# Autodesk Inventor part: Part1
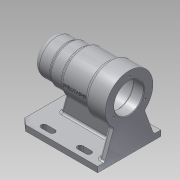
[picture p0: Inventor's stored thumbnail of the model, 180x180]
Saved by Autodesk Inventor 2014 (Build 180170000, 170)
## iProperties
Created: 2017-09
Part Number: Part1
Material: Aluminum 6061
Document SubType Name: Modeling
Designer: user
Density: 2.71 g/cm^3
Appearance: Aluminum - Flat
Author: user
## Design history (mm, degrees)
sketch "Sketch3"
  geometry: L1 (0, 0)-(0, 90); L2 (0, 90)-(112, 90); L3 (112, 90)-(112, 0); L4 (112, 0)-(0, 0)
  constraints: 8 end point
extrude "Extrusion1" new body sketch "Sketch3" distance "d0" = 8; taper "d1" = 0 deg
sketch "Sketch4"
  geometry: L1 (0, 90)-(0, 0) reference; L2 (0, 0)-(112, 0) reference; L3 (112, 90)-(0, 90) reference; L4 (56, 45)-(0, 45); L5 (0, 45)-(0, 81.946); L6 (0, 81.946)-(8.896, 90); L7 (8.896, 90)-(56, 90); L8 (56, 90)-(56, 45); L9 (0, 90)-(8.896, 90); L10 (0, 81.946)-(0, 90); L11 (56, 90)-(112, 90); L12 (0, 45)-(0, 8.054); L13 (0, 8.054)-(8.896, 0); L14 (0, 8.054)-(0, 0); L15 (0, 0)-(8.896, 0); L16 (0, 45)-(0, 81.946); L17 (0, 45)-(0, 8.054)
  constraints: 28 end point, 4 point on line, 2 midpoint
  dimensions: "d3" = 12 distance of L5.end L6.end; "d4" = 12 distance of L12.end L13.end
extrude "Extrusion2" cut sketch "Sketch4" distance "d5" = 8; taper "d6" = 0 deg
workplane "Work Plane1"
sketch "Sketch5"
  geometry: L1 (8.896, 90)-(0, 81.946) reference; L2 (0, 81.946)-(0, 8.054) reference; L3 (0, 8.054)-(8.896, 0) reference; L4 (8.896, 0)-(112, 0) reference; L5 (112, 0)-(112, 90) reference; L6 (112, 90)-(8.896, 90) reference; L7 (112, 90)-(112, 45); L8 (112, 45)-(112, 75); L9 (112, 45)-(0, 45); L10 (0, 45)-(0, 70); L11 (0, 70)-(25, 70); L12 (25, 70)-(25, 72); L13 (25, 72)-(45, 72); L14 (45, 72)-(45, 75); L15 (45, 75)-(84, 75); L16 (84, 75)-(84, 79); L17 (84, 79)-(112, 79); L18 (112, 79)-(112, 45); L19 (112, 45)-(112, 79); 1 further point
  constraints: 26 end point, 3 point on line, 2 midpoint
revolve "Revolution1" sketch "Sketch5" stored, may be unused: angle "d8" = 90 deg
sketch "Sketch6"
  geometry: C1 r 34 at (0, 0) reference; C2 r 21 at (0, 0); 1 further point
  constraints: 1 centre point, 1 coincident
extrude "Extrusion3" cut sketch "Sketch6" distance "d9" = 15; taper "d10" = 0 deg
sketch "Sketch7"
  geometry: C1 r 21 at (0, 0) reference; C2 r 24 at (0, 0); 1 further point
  constraints: 1 centre point, 1 coincident
extrude "Extrusion4" cut sketch "Sketch7" distance "d11" = 54; taper "d12" = 0 deg
sketch "Sketch8"
  geometry: C1 r 24 at (0, 0) reference; C2 r 21 at (0, 0); 1 further point
  constraints: 1 centre point, 1 coincident
extrude "Extrusion5" cut sketch "Sketch8" distance "d13" = 12; taper "d14" = 0 deg
sketch "Sketch9"
  geometry: C1 r 21 at (0, 0) reference; C2 r 17.5 at (0, 0); 1 further point
  constraints: 1 centre point, 1 coincident
extrude "Extrusion6" cut sketch "Sketch9" distance "d15" = 18; taper "d16" = 0 deg
sketch "Sketch10"
  geometry: C1 r 17.5 at (0, 0) reference; C2 r 16 at (0, 0); 1 further point
  constraints: 1 centre point, 1 coincident
extrude "Extrusion7" cut sketch "Sketch10" distance "d17" = 4; taper "d18" = 0 deg
sketch "Sketch11"
  geometry: C1 r 16 at (0, 0) reference; C2 r 10.5 at (0, 0); 1 further point
  constraints: 1 centre point, 1 coincident
extrude "Extrusion8" cut sketch "Sketch11" distance "d19" = 4; taper "d20" = 0 deg
sketch "Sketch12"
  geometry: L1 (0, 81.946)-(0, 8.054) reference; L2 (0, 45)-(0, 11); L3 (0, 11)-(24, 11); L4 (24, 11)-(36, 11); L5 (24, 15)-(36, 15); L6 (24, 7)-(36, 7); A1 r 4 centre (24, 11) between (24, 15) and (24, 7); A2 r 4 centre (36, 11) between (36, 15) and (36, 7); 1 further point
  constraints: 10 end point, 4 point on circle, 2 centre point, 2 coincident, 1 midpoint, 1 point on line
extrude "Extrusion9" cut sketch "Sketch12" distance "d21" = 8; taper "d22" = 0 deg
pattern_linear "Rectangular Pattern1" dims "d25" = -68, "d28" = 52
sketch "Sketch13"
  geometry: C1 r 34 at (0, 0) reference; 3 further points
  constraints: 1 coincident, 1 horizontal alignment, 2 other
hole "Hole1" sketch "Sketch13" at (-26, 0) diameter "d29" = 3.242; stored, may be unused: countersink angle "d33" = 90 deg, drill point angle "d35" = 118 deg; dims "d30" = 8, "d31" = 11, "d32" = 2, "d34" = 11
pattern_circular "Circular Pattern1" dims angle "d37" = 360 deg
workplane "Work Plane2"
sketch "Sketch15"
  geometry: L1 (0, 0)-(0, 6.46); L2 (0, 6.46)-(-17.765, 6.46); L3 (-17.765, 6.46)-(-28.215, 45.46); L4 (-112, 104)-(-112, 36) reference; L5 (-28.215, 45.46)-(-112, 45.46); L6 (-112, 45.46)-(-112, 7.935)
  constraints: 10 end point, 1 point on line
  dimensions: "d40" = 39 vertical distance of L2.end L3.end; "d41" = 105 deg angle of L3 L2
feature "Rib1" sketch "Sketch15" dims "d42" = 1, "d43" = 8, "d44" = 0, "d45" = 0, "d46" = 1, "d47" = 1
sketch "Sketch16"
  geometry: L1 (-8, 49)-(-8, 90) reference; L2 (0, 90)-(-8, 90); L3 (-8, 90)-(-8, 80); L4 (-8, 80)-(-48.407, 65.293); L5 (-48.407, 65.293)-(-48.407, 49); L6 (-48.407, 49)-(-8, 49)
  constraints: 10 end point, 1 point on line
feature "Rib2" sketch "Sketch16" dims "d48" = 1, "d49" = 8, "d50" = 0, "d51" = 0, "d52" = 1, "d53" = 1
mirror "Mirror1"
fillet "Fillet1" dims "d54" = 9, "d55" = 3
fillet "Fillet3" dims "d57" = 3
fillet "Fillet4" dims "d58" = 3
fillet "Fillet5" dims "d59" = 3
chamfer "Chamfer1" distance "d60" = 1; stored, may be unused: second distance "d61" = 2, angle "d62" = 45 deg
fillet "Fillet6" dims "d63" = 0.3
fillet "Fillet7" dims "d64" = 3
workplane "Work Plane3"
sketch "Sketch17"
  geometry: L1 (-47.5, 22)-(-47.5, -22) reference; L2 (-47.5, 0)-(0.5, 0); L3 (-16.326, 2.106)-(16.544, 2.106); L4 (16.544, 2.106)-(16.544, -2.736); L5 (16.544, -2.736)-(-16.326, -2.736); L6 (-16.326, -2.736)-(-16.326, 2.106); 1 further point
  constraints: 2 end point, 1 midpoint, 2 other
emboss "Emboss1" sketch "Sketch17" dims "d5" = 8, "d6" = 0, "d65" = 0.5, "d66" = 0
body "Solid1"
node "Projected Loop1"
other parameters: "d39" = 45
